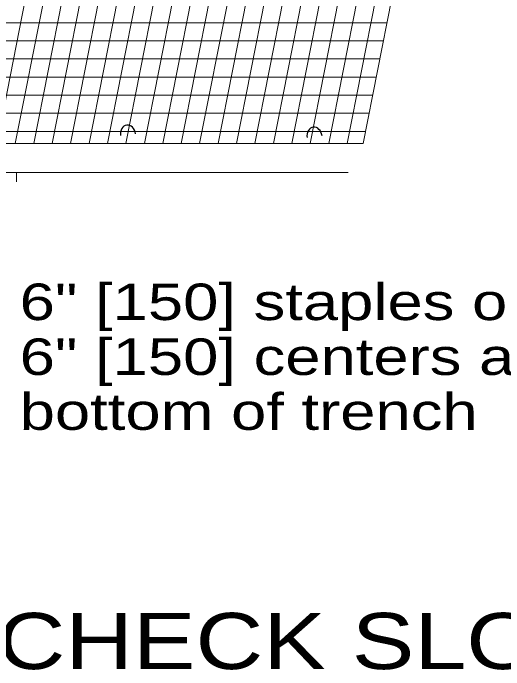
# Model space of a CAD drawing. Extents: x 1083.1 to 1117.1, y 719.4 to 741.4.
# Drawn here: x 1100.133 to 1102.233, y 732.755 to 735.563 of the extents above; entities that cross this region are included whole.
import ezdxf

# ---------------------------------------------------------------- set-up
doc = ezdxf.new("R2010")
doc.units = 0
doc.header["$LTSCALE"] = 0.062
doc.layers.add('1', color=7, linetype='Continuous', lineweight=13)

msp = doc.modelspace()

# ---------------------------------------------------------------- linework, layer by layer
at = {"layer": '1'}
for p, q in [((1100.06375, 735.00583), (1100.73092, 738.38117)), ((1100.14258, 735.00583), (1100.80975, 738.38117)), ((1100.2215, 735.00583), (1100.88867, 738.38117)), ((1100.30033, 735.00583), (1100.9675, 738.38117)), ((1100.37925, 735.00583), (1101.04642, 738.38117)), ((1100.45808, 735.00583), (1101.12533, 738.38117)), ((1100.537, 735.00583), (1101.20417, 738.38117)), ((1100.61583, 735.00583), (1101.283, 738.38117)), ((1100.69475, 735.00583), (1101.36183, 738.38117)), ((1100.77367, 735.00583), (1101.44075, 738.38117)), ((1100.8525, 735.00583), (1101.51958, 738.38117)), ((1100.93142, 735.00583), (1101.5985, 738.38117)), ((1101.01025, 735.00583), (1101.67733, 738.38117)), ((1101.08917, 735.00583), (1101.75625, 738.38117)), ((1101.168, 735.00583), (1101.83517, 738.38117)), ((1101.24692, 735.00583), (1101.914, 738.38117)), ((1101.32575, 735.00583), (1101.99292, 738.38117)), ((1101.40467, 735.00583), (1102.07175, 738.38117)), ((1101.48358, 735.00583), (1102.15067, 738.38117)), ((1101.56233, 735.00583), (1101.96633, 737.04958)), ((1101.63133, 735.00583), (1102.02383, 736.99158)), ((1099.90467, 735.5215), (1101.73317, 735.5215)), ((1099.87242, 735.44417), (1101.71783, 735.44417)), ((1099.82983, 735.36675), (1101.70258, 735.36675)), ((1099.77483, 735.28942), (1101.68725, 735.28942)), ((1099.7015, 735.212), (1101.67192, 735.212)), ((1099.60308, 735.13467), (1101.65675, 735.13467)), ((1099.45367, 735.05733), (1101.64142, 735.05733)), ((1098.48917, 735.00583), (1101.63125, 735.00583)), ((1099.17767, 735.00583), (1101.63125, 735.00583)), ((1098.48917, 734.88167), (1101.56667, 734.88167)), ((1100.14725, 734.841), (1100.14725, 734.88167))]:
    msp.add_line(p, q, dxfattribs=at)
at = {"layer": '1', "lineweight": 25}
for centre in [(1100.62461, 735.04343), (1101.4229, 735.03435)]:
    msp.add_ellipse(centre, major_axis=(-0.00492, 0.04069), ratio=0.788117, start_param=4.7123369, end_param=7.8539295, dxfattribs=at)

# ---------------------------------------------------------------- texts
at = {"layer": '1'}
for s, height, width, p in [('6" [150] staples on', 0.156, 1.3, (1100.16133, 734.25033)), ('6" [150] centers across', 0.156, 1.3, (1100.16133, 734.01567)), ('bottom of trench', 0.156, 1.3, (1100.16133, 733.781)), ('CHECK SLOT CONSTRUCTION DETAILS', 0.24, 1.25, (1100.06667, 732.75808))]:
    msp.add_text(s, height=height, dxfattribs=dict(at, width=width)).set_placement(p)

doc.saveas('drawing.dxf')
